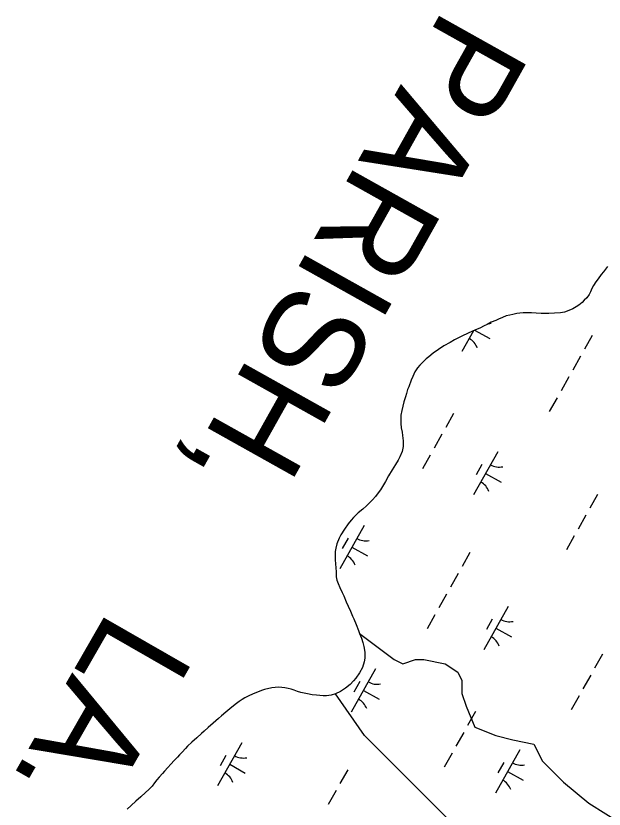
# Model space of a CAD drawing. Extents: x 3913936 to 3933962, y 195330 to 217741.
# Drawn here: x 3923870 to 3924462, y 208082 to 208881 of the extents above; entities that cross this region are included whole.
import ezdxf

# ---------------------------------------------------------------- set-up
doc = ezdxf.new("R2010")
doc.units = 0
for name, color, linetype in [('V-TOPO-GNAM-IDEN', 7, 'Continuous'), ('V-TOPO-SHOR', 7, 'Continuous'), ('V-WETL-SWMP', 7, 'Continuous')]:
    doc.layers.add(name, color=color, linetype=linetype)

msp = doc.modelspace()

# ---------------------------------------------------------------- linework, layer by layer
at = {"layer": 'V-TOPO-SHOR'}
for points in [[(3924215.93, 208258.48), (3924250.84, 208232.33), (3924259.36, 208228.08), (3924272.14, 208232.33), (3924280.65, 208232.33), (3924301.95, 208228.08), (3924314.72, 208219.56), (3924318.98, 208211.04), (3924318.98, 208202.52), (3924318.98, 208198.26), (3924323.24, 208185.49), (3924331.76, 208164.2), (3924353.05, 208155.68), (3924370.09, 208151.42), (3924391.38, 208147.16), (3924399.9, 208130.13), (3924421.19, 208108.83), (3924446.74, 208087.54), (3924480.81, 208066.25)], [(3924463.78, 207810.73), (3924455.26, 207840.54), (3924442.48, 207874.61), (3924421.19, 207929.97), (3924365.83, 208010.89), (3924331.76, 208044.95), (3924297.69, 208079.02), (3924250.84, 208125.87), (3924221.03, 208155.68), (3924191.68, 208197.75)]]:
    msp.add_lwpolyline(points, dxfattribs=at)
at = {"layer": 'V-WETL-SWMP'}
for p, q in [((3924465.3, 208628.03), (3924461.34, 208622.82)), ((3924459.17, 208619.96), (3924455.98, 208615.79)), ((3924461.34, 208622.82), (3924459.17, 208619.96)), ((3924453.68, 208612.54), (3924451.39, 208608.9)), ((3924455.98, 208615.79), (3924453.68, 208612.54)), ((3924448.35, 208602.8), (3924446.95, 208599.94)), ((3924449.48, 208605.91), (3924448.35, 208602.8)), ((3924451.39, 208608.9), (3924449.48, 208605.91)), ((3924442.09, 208594.33), (3924439.92, 208591.99)), ((3924444.53, 208596.55), (3924442.09, 208594.33)), ((3924446.95, 208599.94), (3924444.53, 208596.55)), ((3924434.01, 208587.54), (3924430.67, 208585.57)), ((3924436.71, 208589.37), (3924434.01, 208587.54)), ((3924439.92, 208591.99), (3924436.71, 208589.37)), ((3924363.39, 208578.35), (3924359.79, 208576.89)), ((3924367, 208579.28), (3924363.39, 208578.35)), ((3924370.1, 208579.96), (3924367, 208579.28)), ((3924374.23, 208580.65), (3924370.1, 208579.96)), ((3924377.33, 208581.06), (3924374.23, 208580.65)), ((3924380.69, 208581.35), (3924377.33, 208581.06)), ((3924388.83, 208581.43), (3924380.69, 208581.35)), ((3924393.62, 208581.08), (3924388.83, 208581.43)), ((3924398.66, 208580.87), (3924393.62, 208581.08)), ((3924403.18, 208580.92), (3924398.66, 208580.87)), ((3924406.41, 208580.82), (3924403.18, 208580.92)), ((3924412.23, 208581), (3924406.41, 208580.82)), ((3924418.17, 208581.44), (3924412.23, 208581)), ((3924422.17, 208582.26), (3924418.17, 208581.44)), ((3924426.55, 208583.72), (3924422.17, 208582.26)), ((3924430.67, 208585.57), (3924426.55, 208583.72)), ((3924348.33, 208572), (3924344.34, 208569.9)), ((3924352.97, 208573.85), (3924348.33, 208572)), ((3924355.67, 208575.17), (3924352.97, 208573.85)), ((3924359.79, 208576.89), (3924355.67, 208575.17)), ((3924330.71, 208563.52), (3924318.9, 208542.51)), ((3924329.67, 208563.04), (3924324.65, 208560.79)), ((3924332.5, 208564.36), (3924329.67, 208563.04)), ((3924331.71, 208563.99), (3924346.84, 208555.48)), ((3924337.01, 208566.21), (3924332.5, 208564.36)), ((3924341.25, 208568.32), (3924337.01, 208566.21)), ((3924344.34, 208569.9), (3924341.25, 208568.32)), ((3924311.4, 208554.21), (3924307.03, 208551.71)), ((3924319.38, 208558.29), (3924311.4, 208554.21)), ((3924324.65, 208560.79), (3924319.38, 208558.29)), ((3924449.99, 208558.78), (3924442.15, 208544.83)), ((3924300.86, 208548.16), (3924295.2, 208544.49)), ((3924307.03, 208551.71), (3924300.86, 208548.16)), ((3924289.94, 208540.82), (3924285.58, 208537.29)), ((3924295.2, 208544.49), (3924289.94, 208540.82)), ((3924278.78, 208531.15), (3924276.48, 208528.93)), ((3924282.88, 208535.07), (3924278.78, 208531.15)), ((3924285.58, 208537.29), (3924282.88, 208535.07)), ((3924438.23, 208537.86), (3924430.39, 208523.91)), ((3924274.18, 208525.94), (3924271.63, 208521.91)), ((3924276.48, 208528.93), (3924274.18, 208525.94)), ((3924269.48, 208517.49), (3924267.96, 208513.73)), ((3924271.63, 208521.91), (3924269.48, 208517.49)), ((3924426.47, 208516.94), (3924418.63, 208502.99)), ((3924265.44, 208506.98), (3924264.3, 208504.13)), ((3924267.96, 208513.73), (3924265.44, 208506.98)), ((3924263.17, 208500.37), (3924262.04, 208497)), ((3924264.3, 208504.13), (3924263.17, 208500.37)), ((3924260.54, 208491.94), (3924259.29, 208487.54)), ((3924262.04, 208497), (3924260.54, 208491.94)), ((3924414.71, 208496.02), (3924406.87, 208482.07)), ((3924258.29, 208483), (3924257.56, 208478.47)), ((3924259.29, 208487.54), (3924258.29, 208483)), ((3924257.46, 208475.24), (3924257.38, 208470.07)), ((3924257.56, 208478.47), (3924257.46, 208475.24)), ((3924310.45, 208480.11), (3924302.61, 208466.16)), ((3924257.38, 208470.07), (3924257.81, 208465.68)), ((3924257.81, 208465.68), (3924258.63, 208461.16)), ((3924258.63, 208461.16), (3924259.17, 208458.07)), ((3924298.69, 208459.19), (3924290.85, 208445.24)), ((3924259.17, 208458.07), (3924259.87, 208452.51)), ((3924259.87, 208452.51), (3924259.67, 208446.95)), ((3924259.67, 208446.95), (3924258.68, 208441.9)), ((3924256.4, 208436.32), (3924254.75, 208433.08)), ((3924258.68, 208441.9), (3924256.4, 208436.32)), ((3924286.93, 208438.27), (3924279.09, 208424.32)), ((3924355.03, 208441.63), (3924330.53, 208398.04)), ((3924252.21, 208428.79), (3924248.64, 208423.33)), ((3924254.75, 208433.08), (3924252.21, 208428.79)), ((3924338.99, 208428.84), (3924333.11, 208418.38)), ((3924248.64, 208423.33), (3924244.95, 208417.22)), ((3924342.78, 208419.83), (3924358.47, 208411.01)), ((3924241.9, 208411.5), (3924239.86, 208408.12)), ((3924244.95, 208417.22), (3924241.9, 208411.5)), ((3924236.94, 208403.31), (3924233.62, 208398.89)), ((3924239.86, 208408.12), (3924236.94, 208403.31)), ((3924231.83, 208396.41), (3924229.02, 208393.15)), ((3924233.62, 208398.89), (3924231.83, 208396.41)), ((3924455.45, 208398.6), (3924447.61, 208384.65)), ((3924222.74, 208387.02), (3924219.15, 208383.89)), ((3924225.69, 208389.76), (3924222.74, 208387.02)), ((3924229.02, 208393.15), (3924225.69, 208389.76)), ((3924214.53, 208379.96), (3924209.92, 208375.4)), ((3924219.15, 208383.89), (3924214.53, 208379.96)), ((3924207.36, 208372.79), (3924204.43, 208369.01)), ((3924209.92, 208375.4), (3924207.36, 208372.79)), ((3924443.69, 208377.68), (3924435.85, 208363.73)), ((3924220.43, 208367.34), (3924195.93, 208323.75)), ((3924200.6, 208363.68), (3924197.16, 208357.96)), ((3924204.43, 208369.01), (3924200.6, 208363.68)), ((3924195.38, 208354.45), (3924193.11, 208349)), ((3924197.16, 208357.96), (3924195.38, 208354.45)), ((3924204.39, 208354.55), (3924198.51, 208344.09)), ((3924431.93, 208356.76), (3924424.09, 208342.81)), ((3924193.11, 208349), (3924191.86, 208344.59)), ((3924191.37, 208340.97), (3924191.28, 208337.22)), ((3924191.86, 208344.59), (3924191.37, 208340.97)), ((3924208.18, 208345.54), (3924223.87, 208336.72)), ((3924327.02, 208340.02), (3924319.18, 208326.07)), ((3924191.28, 208337.22), (3924191.45, 208332.96)), ((3924191.45, 208332.96), (3924191.75, 208328.44)), ((3924191.75, 208328.44), (3924192.04, 208324.95)), ((3924192.04, 208324.95), (3924192.21, 208320.17)), ((3924192.21, 208320.17), (3924192.39, 208315.64)), ((3924192.39, 208315.64), (3924193.19, 208312.29)), ((3924315.26, 208319.1), (3924307.42, 208305.15)), ((3924193.19, 208312.29), (3924194.52, 208308.94)), ((3924194.52, 208308.94), (3924196.11, 208304.82)), ((3924196.11, 208304.82), (3924198.35, 208299.8)), ((3924198.35, 208299.8), (3924199.93, 208296.46)), ((3924199.93, 208296.46), (3924202.57, 208290.53)), ((3924202.57, 208290.53), (3924204.43, 208286.16)), ((3924303.5, 208298.18), (3924295.66, 208284.23)), ((3924204.43, 208286.16), (3924206.67, 208280.88)), ((3924365.42, 208285.83), (3924340.92, 208242.24)), ((3924206.67, 208280.88), (3924208.78, 208276.12)), ((3924208.78, 208276.12), (3924210.23, 208273.16)), ((3924291.74, 208277.26), (3924283.9, 208263.31)), ((3924210.23, 208273.16), (3924212.61, 208267.49)), ((3924212.61, 208267.49), (3924214.74, 208261.69)), ((3924349.39, 208273.05), (3924343.51, 208262.58)), ((3924214.74, 208261.69), (3924215.93, 208258.47)), ((3924215.93, 208258.47), (3924217.78, 208253.84)), ((3924353.17, 208264.03), (3924368.86, 208255.21)), ((3924217.78, 208253.84), (3924219.12, 208249.33)), ((3924219.12, 208249.33), (3924220.19, 208245.33)), ((3924220.19, 208245.33), (3924221.15, 208239.78)), ((3924221.15, 208239.78), (3924221.33, 208233.71)), ((3924460.26, 208237.59), (3924452.42, 208223.64)), ((3924220.59, 208230.08), (3924218.71, 208224.25)), ((3924221.33, 208233.71), (3924220.59, 208230.08)), ((3924232.06, 208222.87), (3924207.55, 208179.28)), ((3924215.78, 208218.79), (3924212.08, 208213.58)), ((3924218.71, 208224.25), (3924215.78, 208218.79)), ((3924209.65, 208210.72), (3924206.33, 208207.33)), ((3924212.08, 208213.58), (3924209.65, 208210.72)), ((3924448.5, 208216.67), (3924440.65, 208202.72)), ((3924127.51, 208203.88), (3924120.29, 208202)), ((3924131, 208204.3), (3924127.51, 208203.88)), ((3924134.35, 208204.46), (3924131, 208204.3)), ((3924137.72, 208204.23), (3924134.35, 208204.46)), ((3924140.82, 208203.87), (3924137.72, 208204.23)), ((3924144.19, 208203.26), (3924140.82, 208203.87)), ((3924147.17, 208202.38), (3924144.19, 208203.26)), ((3924201.84, 208203.54), (3924196.83, 208200.13)), ((3924206.33, 208207.33), (3924201.84, 208203.54)), ((3924216.02, 208210.09), (3924210.14, 208199.62)), ((3924103.93, 208195.51), (3924100.59, 208193.8)), ((3924108.83, 208197.76), (3924103.93, 208195.51)), ((3924113.2, 208199.48), (3924108.83, 208197.76)), ((3924117.2, 208201.06), (3924113.2, 208199.48)), ((3924120.29, 208202), (3924117.2, 208201.06)), ((3924150.15, 208201.37), (3924147.17, 208202.38)), ((3924153.4, 208200.24), (3924150.15, 208201.37)), ((3924156.64, 208199.24), (3924153.4, 208200.24)), ((3924160, 208198.36), (3924156.64, 208199.24)), ((3924163.63, 208197.62), (3924160, 208198.36)), ((3924168.29, 208196.89), (3924163.63, 208197.62)), ((3924172.56, 208196.54), (3924168.29, 208196.89)), ((3924175.92, 208196.18), (3924172.56, 208196.54)), ((3924179.42, 208195.7), (3924175.92, 208196.18)), ((3924182.65, 208195.6), (3924179.42, 208195.7)), ((3924187.17, 208196.29), (3924182.65, 208195.6)), ((3924191.68, 208197.75), (3924187.17, 208196.29)), ((3924196.83, 208200.13), (3924191.68, 208197.75)), ((3924219.81, 208201.07), (3924235.5, 208192.25)), ((3924436.73, 208195.75), (3924428.89, 208181.8)), ((3924092.11, 208188.03), (3924089.03, 208185.55)), ((3924094.68, 208190), (3924092.11, 208188.03)), ((3924097.63, 208192.09), (3924094.68, 208190)), ((3924100.59, 208193.8), (3924097.63, 208192.09)), ((3924081.21, 208179.4), (3924076.85, 208175.48)), ((3924085.31, 208182.67), (3924081.21, 208179.4)), ((3924089.03, 208185.55), (3924085.31, 208182.67)), ((3924332.48, 208179.84), (3924324.64, 208165.9)), ((3924073.9, 208172.87), (3924068.64, 208168.17)), ((3924076.85, 208175.48), (3924073.9, 208172.87)), ((3924063.64, 208163.73), (3924059.67, 208160.33)), ((3924068.64, 208168.17), (3924063.64, 208163.73)), ((3924056.85, 208157.71), (3924051.98, 208153.4)), ((3924059.67, 208160.33), (3924056.85, 208157.71)), ((3924320.72, 208158.92), (3924312.88, 208144.97)), ((3924047.24, 208148.96), (3924042.88, 208144.92)), ((3924051.98, 208153.4), (3924047.24, 208148.96)), ((3924097.45, 208148.58), (3924072.95, 208104.99)), ((3924037.25, 208138.92), (3924034.69, 208136.31)), ((3924040.71, 208142.57), (3924037.25, 208138.92)), ((3924042.88, 208144.92), (3924040.71, 208142.57)), ((3924377.05, 208141.36), (3924352.55, 208097.77)), ((3924029.44, 208130.7), (3924026.11, 208127.05)), ((3924032.64, 208134.09), (3924029.44, 208130.7)), ((3924034.69, 208136.31), (3924032.64, 208134.09)), ((3924081.42, 208135.8), (3924075.54, 208125.33)), ((3924308.96, 208138), (3924301.12, 208124.05)), ((3924022.79, 208123.53), (3924019.72, 208119.75)), ((3924026.11, 208127.05), (3924022.79, 208123.53)), ((3924085.2, 208126.78), (3924100.89, 208117.96)), ((3924361.02, 208128.58), (3924355.14, 208118.12)), ((3924017.54, 208117.41), (3924014.34, 208114.02)), ((3924019.72, 208119.75), (3924017.54, 208117.41)), ((3924204.04, 208121.26), (3924196.2, 208107.32)), ((3924364.8, 208119.57), (3924380.49, 208110.74)), ((3924009.49, 208108.02), (3924007.06, 208104.64)), ((3924012.04, 208111.28), (3924009.49, 208108.02)), ((3924014.34, 208114.02), (3924012.04, 208111.28)), ((3924003.99, 208101.51), (3924000.53, 208098.51)), ((3924007.06, 208104.64), (3924003.99, 208101.51)), ((3924192.28, 208100.34), (3924184.44, 208086.39)), ((3923995.66, 208094.19), (3923990.66, 208089.75)), ((3924000.53, 208098.51), (3923995.66, 208094.19)), ((3923986.04, 208085.44), (3923982.07, 208081.66)), ((3923990.66, 208089.75), (3923986.04, 208085.44))]:
    msp.add_line(p, q, dxfattribs=at)
for centre, start, end in [((3924344.89, 208588.26), 272.95344, 281.42974), ((3924317.82, 208540.11), 19.88608, 61.42973), ((3924356.52, 208443.79), 239.88608, 281.42974), ((3924329.45, 208395.64), 19.88608, 61.42973), ((3924221.92, 208369.5), 239.88608, 281.42974), ((3924194.85, 208321.35), 19.88608, 61.42973), ((3924366.92, 208288), 239.88608, 281.42974), ((3924339.85, 208239.84), 19.88608, 61.42973), ((3924233.55, 208225.04), 239.88608, 281.42974), ((3924206.48, 208176.88), 19.88608, 61.42973), ((3924098.94, 208150.75), 239.88608, 281.42974), ((3924378.55, 208143.53), 239.88608, 281.42974), ((3924071.87, 208102.59), 19.88608, 61.42973), ((3924351.48, 208095.37), 19.88608, 61.42973)]:
    msp.add_arc(centre, 17.62, start, end, dxfattribs=at)

# ---------------------------------------------------------------- texts
at = {"layer": 'V-TOPO-GNAM-IDEN'}
for s, rotation, p in [('PARISH,', 240.73851, (3924301.24, 208890.13)), ('LA.', 240.13851, (3923963.89, 208284.14))]:
    msp.add_text(s, height=100, rotation=rotation, dxfattribs=at).set_placement(p)

doc.saveas('drawing.dxf')
